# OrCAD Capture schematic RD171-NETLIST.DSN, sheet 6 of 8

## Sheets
6 3: size A3
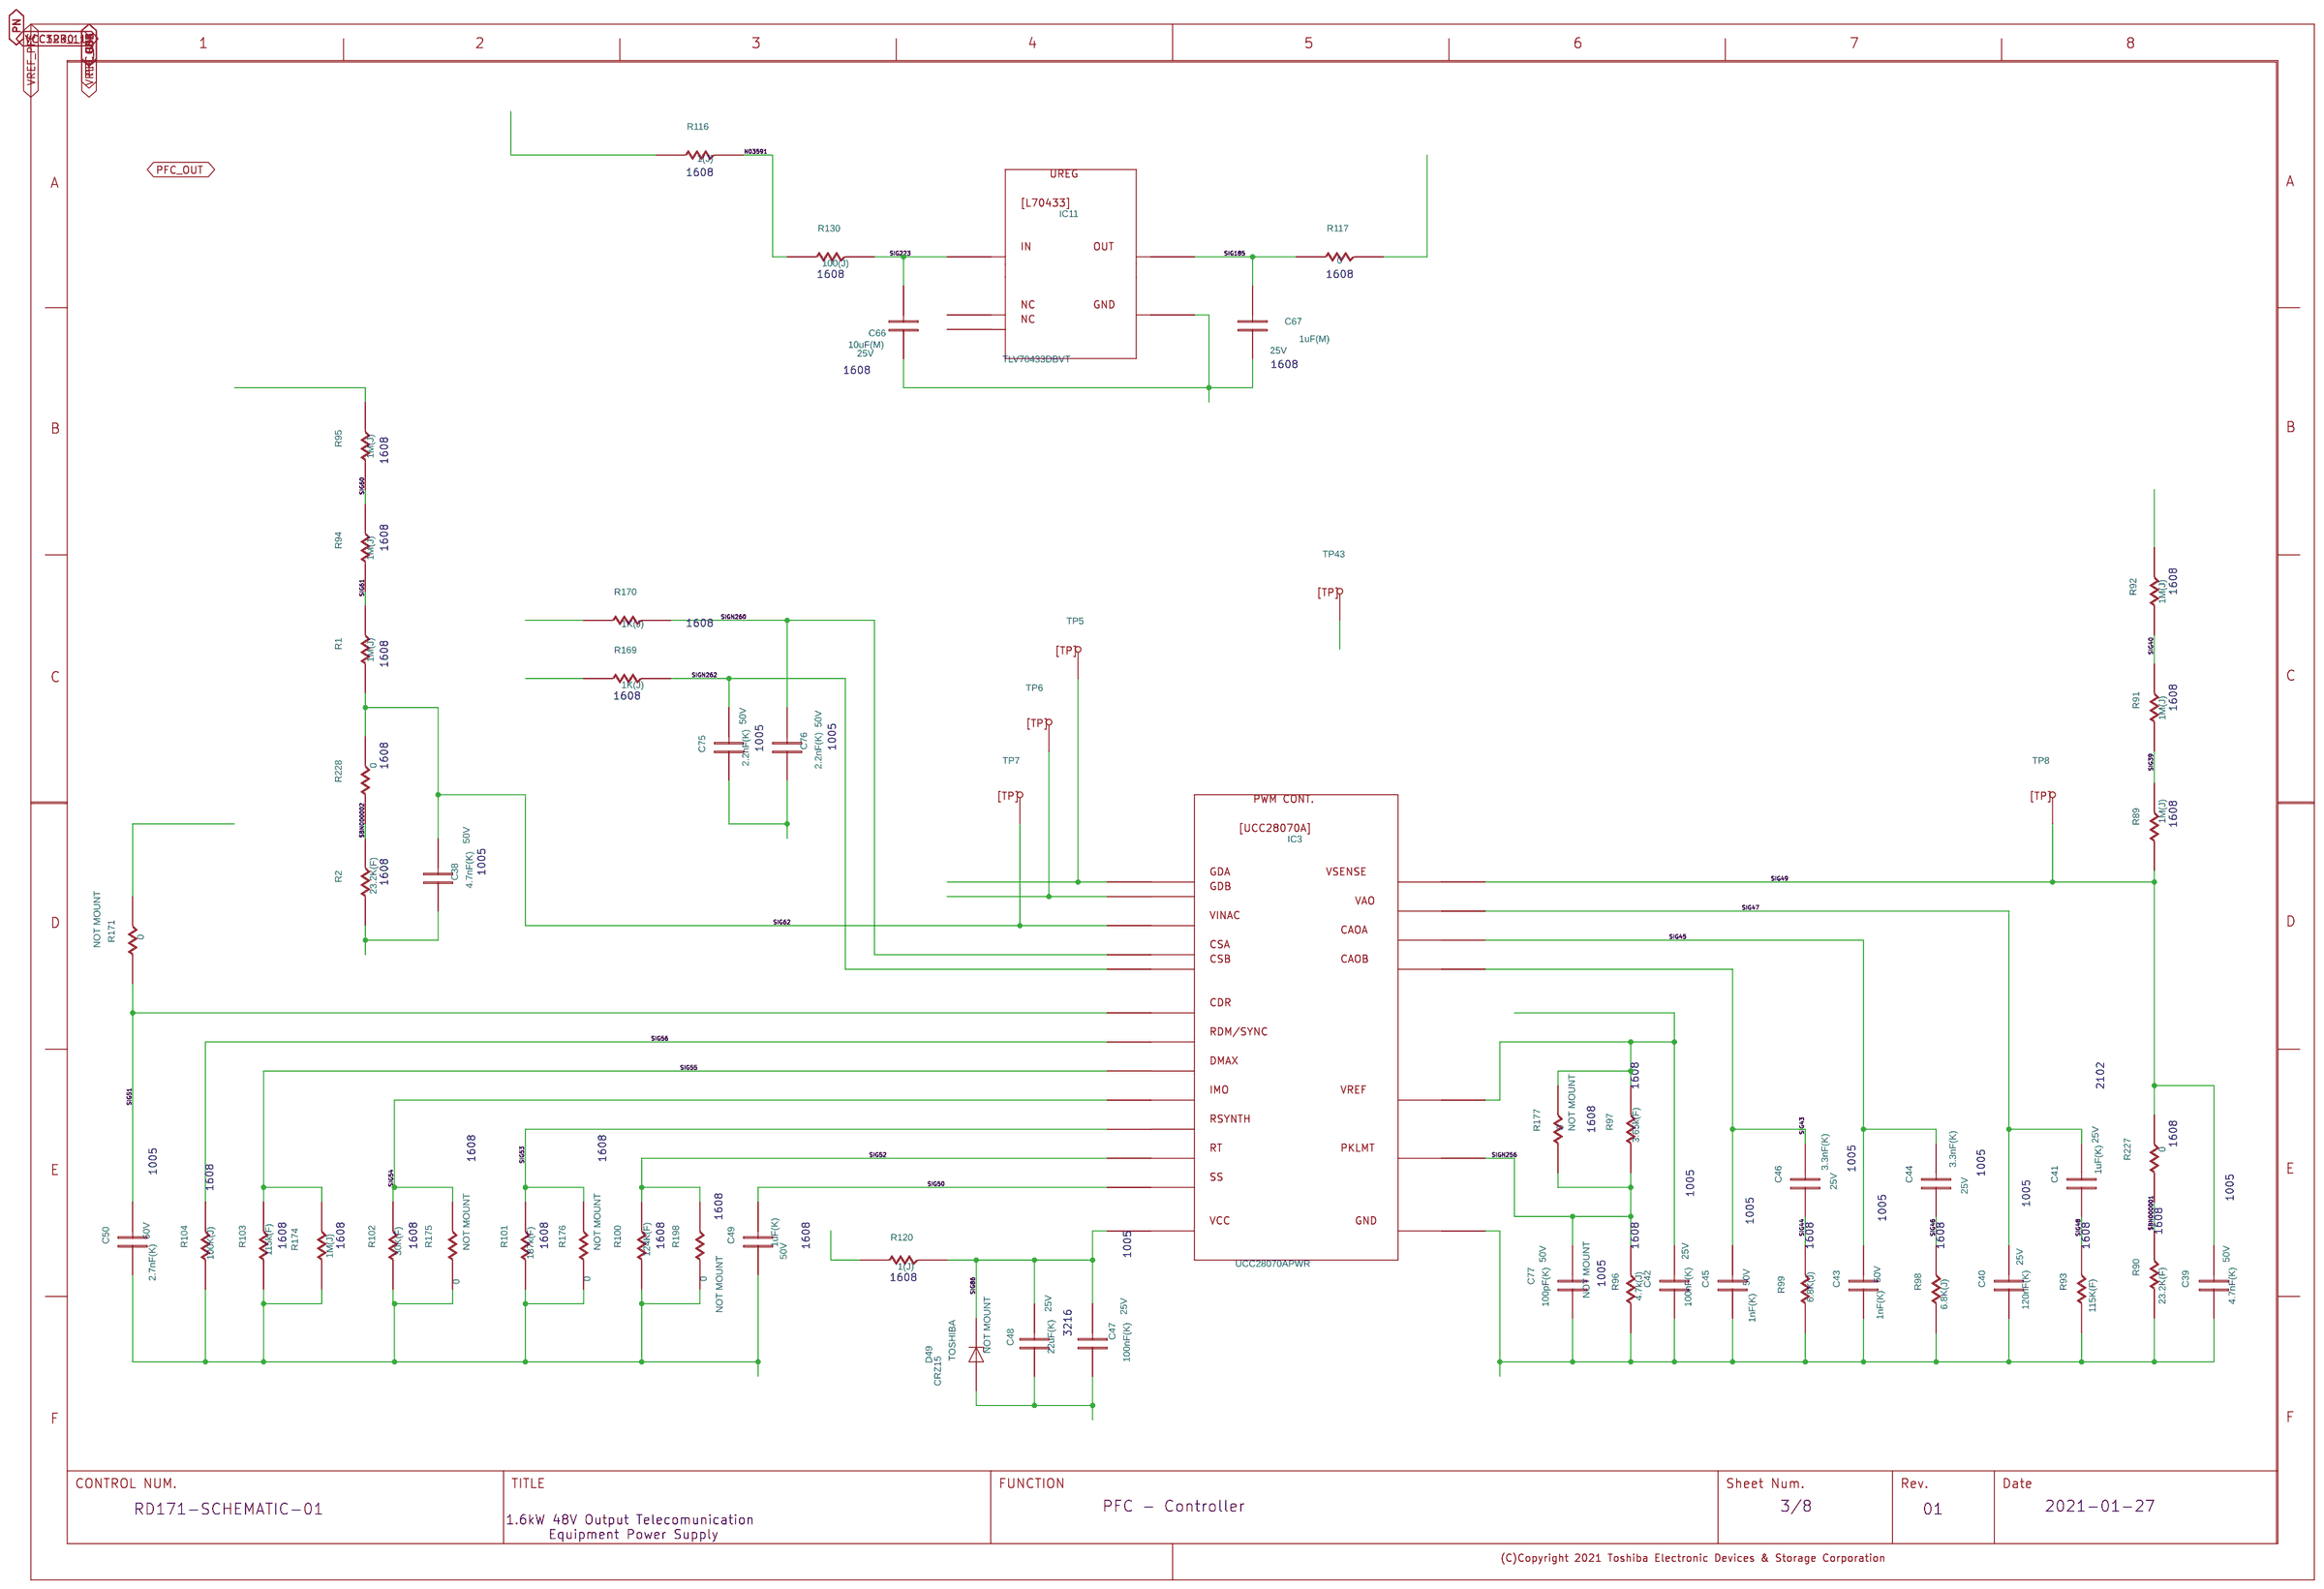
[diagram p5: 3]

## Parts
C38  4.7nF
C39  4.7nF
C40  120nF
C41  1uF
C42  100nF
C43  1nF
C44  3.3nF
C45  1nF
C46  3.3nF
C47  100nF
C48  22uF
C49  1uF  [C1608JB1H105K080AB]
C50  2.7nF
C66  10uF
C67  1uF
C75  2.2nF
C76  2.2nF
C77  100pF
D49  D49  [CRZ15]
IC3  IC3  [UCC28070APWR]
IC11  IC11  [TLV70433DBVT]
R1  1M
R2  23.2K
R89  1M
R90  23.2K
R91  1M
R92  1M
R93  115k
R94  1M
R95  1M
R96  4.3k
R97  3.65k
R98  6.8k
R99  6.8k
R100  124k
R101  187k
R102  30k
R103  115k
R104  100k
R116  1
R117  0
R120  1
R130  100
R169  1k
R170  1k
R171  0
R174  1M
R175  0
R176  0
R177  0
R198  0
R227  0
R228  0
TP5  TP5  [HK-2-S]
TP6  TP6  [HK-2-S]
TP7  TP7  [HK-2-S]
TP8  TP8  [HK-2-S]
TP43  TP43  [LC-22-S-WHITE]
U?#5  WAKU_DEF100

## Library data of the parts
C38 = C: ADSMODELNAME: s_UMK105BJ122KV_F; CAPACITANCETOLE: K; CDMASTERCADCELG: KC0005; CHIPSIZE: 1005; COMP: PRT_52; COMPONENTNAME: C_C.Normal_package; FNLEADFREETHET1GT2GMCTH1: 2_0_N; FUNCTION: C_C.Normal_package; GCOUNT: 1; INSTANCENAME: INS2671; MAKER: TDK; MAXGCOUNT: 1; NOMINALCAPACITA: 1.2n; OUMECLASSIFICATION: ƒZƒ‰ƒ~ƒbƒNƒRƒ“ƒfƒ“ƒT; OUMEMAKER: TYD ‘¾—z—U“d; OUMEMAKERKATAMEI: UMK105BJ122KV-F; PARTNAME: Chip1005_GS_2; PMPRODUCTSTYPEG: HD1; QUADMODEL: CON_1.2N; RATEDVOLTAGE: 50; SIZECODESMD: 1005; TEMPCHARACTERI2: B; VAL1: 4.7nF(K); VAL2: 50V; VAL3: GRM155R71H472JA01D
C39 = C: ADSMODELNAME: s_UMK105BJ122KV_F; CAPACITANCETOLE: K; CDMASTERCADCELG: KC0005; CHIPSIZE: 1005; COMP: PRT_52; COMPONENTNAME: C_C.Normal_package; FNLEADFREETHET1GT2GMCTH1: 2_0_N; FUNCTION: C_C.Normal_package; GCOUNT: 1; INSTANCENAME: INS2681; MAKER: TDK; MAXGCOUNT: 1; NOMINALCAPACITA: 1.2n; OUMECLASSIFICATION: ƒZƒ‰ƒ~ƒbƒNƒRƒ“ƒfƒ“ƒT; OUMEMAKER: TYD ‘¾—z—U“d; OUMEMAKERKATAMEI: UMK105BJ122KV-F; PARTNAME: Chip1005_GS_2; PMPRODUCTSTYPEG: HD1; QUADMODEL: CON_1.2N; RATEDVOLTAGE: 50; SIZECODESMD: 1005; TEMPCHARACTERI2: B; VAL1: 4.7nF(K); VAL2: 50V; VAL3: GRM155R71H472JA01D
C40 = C: ADSMODELNAME: s_GCM188R71E154KA37D; CAPACITANCETOLE: K; CDMASTERCADCELG: KC0008; CHIPSIZE: 1608; COMP: PRT_48; COMPONENTNAME: C_C.Normal_package; FNLEADFREETHET1GT2GMCTH1: N_N_N; FUNCTION: C_C.Normal_package; GCOUNT: 1; INSTANCENAME: INS2519; MAKER: MURATA; MAXGCOUNT: 1; NOMINALCAPACITA: 150n; OUMECLASSIFICATION: ƒZƒ‰ƒ~ƒbƒNƒRƒ“ƒfƒ“ƒT; OUMEMAKER: MRT ºc»ì; OUMEMAKERKATAMEI: GCM188R71E154KA37D; PARTNAME: Chip1608_GS_1; PMPRODUCTSTYPEG: DME; QUADMODEL: CON_150N; RATEDVOLTAGE: 25; SIZECODESMD: 1608; VAL1: 120nF(K); VAL2: 25V; VAL3: GRM188R71E124KA01D
C41 = C: ADSMODELNAME: s_GCM31CR71H155KA55L; CAPACITANCETOLE: K; CHIPSIZE: 2012; COMP: PRT_32; COMPONENTNAME: C_C.Normal_package; FUNCTION: C_C.Normal_package; GCOUNT: 1; INSTANCENAME: INS2529; MAKER: TDK; MAXGCOUNT: 1; NOMINALCAPACITA: 1.5u; PARTNAME: Chip2012_GS_1; PMPRODUCTSTYPEG: DME; RATEDVOLTAGE: 50; VAL1: 1uF(K); VAL2: 25V; VAL3: C2012X7R1E105K125AB
C42 = C: ADSMODELNAME: s_GRM155R71E104KE14D; CAPACITANCETOLE: K; CDMASTERCADCELG: KC0005; CHIPSIZE: 1005; COMP: PRT_52; COMPONENTNAME: C_C.Normal_package; FNLEADFREETHET1GT2GMCTH1: N_N_N; FUNCTION: C_C.Normal_package; GCOUNT: 1; INSTANCENAME: INS2499; MAKER: TDK; MAXGCOUNT: 1; NOMINALCAPACITA: 100n; OUMECLASSIFICATION: ƒZƒ‰ƒ~ƒbƒNƒRƒ“ƒfƒ“ƒT; OUMEMAKER: MRT ºc»ì; OUMEMAKERKATAMEI: GRM155R71E104KE14D; PARTNAME: Chip1005_GS_2; QUADMODEL: CON_100N; RATEDVOLTAGE: 25; SIZECODESMD: 1005; VAL1: 100nF(K); VAL2: 25V; VAL3: C1005X7R1E104K050BB
C43 = C: ADSMODELNAME: s_UMK105BJ102KV_F; CAPACITANCETOLE: K; CDMASTERCADCELG: KC0005; CHIPSIZE: 1005; COMP: PRT_52; COMPONENTNAME: C_C.Normal_package; FNLEADFREETHET1GT2GMCTH1: 2_0_N; FUNCTION: C_C.Normal_package; GCOUNT: 1; INSTANCENAME: INS2651; MAKER: TDK; MAXGCOUNT: 1; NOMINALCAPACITA: 1n; OUMECLASSIFICATION: ƒZƒ‰ƒ~ƒbƒNƒRƒ“ƒfƒ“ƒT; OUMEMAKER: TYD ‘¾—z—U“d; OUMEMAKERKATAMEI: UMK105BJ102KV-F; PARTNAME: Chip1005_GS_2; PMPRODUCTSTYPEG: HD1-PC1; QUADMODEL: CON_1N; RATEDVOLTAGE: 50; SIZECODESMD: 1005; TEMPCHARACTERI2: B; VAL1: 1nF(K); VAL2: 50V; VAL3: UMK105BJ102KV-F
C44 = C: ADSMODELNAME: s_C1005JB1E332KT; CAPACITANCETOLE: K; CDMASTERCADCELG: KC0005; CHIPSIZE: 1005; COMP: PRT_52; COMPONENTNAME: C_C.Normal_package; FNLEADFREETHET1GT2GMCTH1: N_N_N; FUNCTION: C_C.Normal_package; GCOUNT: 1; INSTANCENAME: INS2893; MAKER: TDK; MAXGCOUNT: 1; NOMINALCAPACITA: 3.3n; OUMECLASSIFICATION: ƒZƒ‰ƒ~ƒbƒNƒRƒ“ƒfƒ“ƒT; OUMEMAKER: TDK ‚s‚c‚j; OUMEMAKERKATAMEI: C1005JB1E332KT; PARTNAME: Chip1005_GS_2; QUADMODEL: CON_3.3N; RATEDVOLTAGE: 25; SIZECODESMD: 1005; VAL1: 3.3nF(K); VAL2: 25V; VAL3: CGJ2B2X7R1E332K050BA
C45 = C: ADSMODELNAME: s_UMK105BJ102KV_F; CAPACITANCETOLE: K; CDMASTERCADCELG: KC0005; CHIPSIZE: 1005; COMP: PRT_52; COMPONENTNAME: C_C.Normal_package; FNLEADFREETHET1GT2GMCTH1: 2_0_N; FUNCTION: C_C.Normal_package; GCOUNT: 1; INSTANCENAME: INS2661; MAKER: TDK; MAXGCOUNT: 1; NOMINALCAPACITA: 1n; OUMECLASSIFICATION: ƒZƒ‰ƒ~ƒbƒNƒRƒ“ƒfƒ“ƒT; OUMEMAKER: TYD ‘¾—z—U“d; OUMEMAKERKATAMEI: UMK105BJ102KV-F; PARTNAME: Chip1005_GS_2; PMPRODUCTSTYPEG: HD1-PC1; QUADMODEL: CON_1N; RATEDVOLTAGE: 50; SIZECODESMD: 1005; TEMPCHARACTERI2: B; VAL1: 1nF(K); VAL2: 50V; VAL3: UMK105BJ102KV-F
C46 = C: ADSMODELNAME: s_C1005JB1E332KT; CAPACITANCETOLE: K; CDMASTERCADCELG: KC0005; CHIPSIZE: 1005; COMP: PRT_52; COMPONENTNAME: C_C.Normal_package; FNLEADFREETHET1GT2GMCTH1: N_N_N; FUNCTION: C_C.Normal_package; GCOUNT: 1; INSTANCENAME: INS2883; MAKER: TDK; MAXGCOUNT: 1; NOMINALCAPACITA: 3.3n; OUMECLASSIFICATION: ƒZƒ‰ƒ~ƒbƒNƒRƒ“ƒfƒ“ƒT; OUMEMAKER: TDK ‚s‚c‚j; OUMEMAKERKATAMEI: C1005JB1E332KT; PARTNAME: Chip1005_GS_2; QUADMODEL: CON_3.3N; RATEDVOLTAGE: 25; SIZECODESMD: 1005; VAL1: 3.3nF(K); VAL2: 25V; VAL3: CGJ2B2X7R1E332K050BA
C47 = C: ADSCNVFLAG: ON; ADSCOMPONENTNAME: C_1005; ADSMODELNAME: s_GRM155R71E104KE14D; CAPACITANCETOLE: K; CDMASTERCADCELG: KC0005; CHIPSIZE: 1005; COMP: PRT_52; COMPONENTNAME: C_C.Normal_package; FNLEADFREETHET1GT2GMCTH1: N_N_N; FUNCTION: C_C.Normal_package; GCOUNT: 1; ICX_PART_MODEL: CON_100N; INSTANCENAME: INS2489; MAKER: TDK; MAXGCOUNT: 1; NOMINALCAPACITA: 100n; OUMECLASSIFICATION: ƒZƒ‰ƒ~ƒbƒNƒRƒ“ƒfƒ“ƒT; OUMEMAKER: MRT ºc»ì; OUMEMAKERKATAMEI: GRM155R71E104KE14D; PARTNAME: Chip1005_GS_2; QUADMODEL: CON_100N; RATEDVOLTAGE: 25; SIZECODESMD: 1005; SQ_PART_MODEL: CON_100N; VAL1: 100nF(K); VAL2: 25V; VAL3: C1005X7R1E104K050BB
C48 = C: ADSMODELNAME: s_GRM31CB31E226ME15D; CAPACITANCETOLE: M; CDMASTERCADCELG: KC0014; CHIPSIZE: 3216; COMP: PRT_51; COMPONENTNAME: C_C.Normal_package; FNLEADFREETHET1GT2GMCTH1: N_N_N; FUNCTION: C_C.Normal_package; GCOUNT: 1; INSTANCENAME: INS2863; MAKER: MURATA; MAXGCOUNT: 1; NOMINALCAPACITA: 22u; OUMECLASSIFICATION: ƒZƒ‰ƒ~ƒbƒNƒRƒ“ƒfƒ“ƒT; OUMEMAKER: MRT ºc»ì; OUMEMAKERKATAMEI: GRM31CB31E226ME15D; PARTNAME: Chip3216_GS_1; QUADMODEL: CON_22U; RATEDVOLTAGE: 25; SIZECODESMD: 3216; TEMPCHARACTERI2: B; VAL1: 22uF(K); VAL2: 25V; VAL3: GRM31CR61E226KE15L
C49 = C: ADSMODELNAME: s_GRM155R71E104KE14D; CAPACITANCETOLE: K; CDMASTERCADCELG: KC0005; CHIPSIZE: 1005; COMP: PRT_52; COMPONENTNAME: C_C.Normal_package; FNLEADFREETHET1GT2GMCTH1: N_N_N; FUNCTION: C_C.Normal_package; GCOUNT: 1; INSTANCENAME: INS2479; MAKER: TDK; MAXGCOUNT: 1; NOMINALCAPACITA: 100n; OUMECLASSIFICATION: ƒZƒ‰ƒ~ƒbƒNƒRƒ“ƒfƒ“ƒT; OUMEMAKER: MRT ºc»ì; OUMEMAKERKATAMEI: GRM155R71E104KE14D; PARTNAME: Chip1608_GS_1; QUADMODEL: CON_100N; RATEDVOLTAGE: 25; SIZECODESMD: 1005; VAL1: 1uF(K); VAL2: 50V
C50 = C: ADSMODELNAME: s_UMK105BJ272KV_F; CAPACITANCETOLE: K; CDMASTERCADCELG: DC834K; CHIPSIZE: 1005; COMP: PRT_52; COMPONENTNAME: C_C.Normal_package; FNLEADFREETHET1GT2GMCTH1: 3_0_N; FUNCTION: C_C.Normal_package; GCOUNT: 1; INSTANCENAME: INS2711; MAKER: TDK; MAXGCOUNT: 1; NOMINALCAPACITA: 2.7n; OUMECLASSIFICATION: ƒZƒ‰ƒ~ƒbƒNƒRƒ“ƒfƒ“ƒT; OUMEMAKER: TYD ‘¾—z—U“d; OUMEMAKERKATAMEI: UMK105BJ272KV-F; PARTNAME: Chip1005_GS_2; PMPRODUCTSTYPEG: PC1; QUADMODEL: CON_2.7N; RATEDVOLTAGE: 50; SIZECODESMD: 1005; TEMPCHARACTERI2: B; VAL1: 2.7nF(K); VAL2: 50V; VAL3: UMK105BJ272KV-F
C66 = C: ADSMODELNAME: s_ZRB18AR61E106ME01L; CAPACITANCETOLE: M; CDMASTERCADCELG: KC0167; CHIPSIZE: 1608; COMP: PRT_48; COMPONENTNAME: C_C.Normal_package; FNLEADFREETHET1GT2GMCTH1: N_N_N; FUNCTION: C_C.Normal_package; GCOUNT: 1; INSTANCENAME: INS2953; MAKER: TDK; MAXGCOUNT: 1; NOMINALCAPACITA: 10u; OUMECLASSIFICATION: ƒZƒ‰ƒ~ƒbƒNƒRƒ“ƒfƒ“ƒT; OUMEMAKER: MRT ºc»ì; OUMEMAKERKATAMEI: ZRB18AR61E106ME01L; PARTNAME: Chip1608_GS_1; QUADMODEL: CON_10U; RATEDVOLTAGE: 25; SIZECODESMD: 1608; VAL1: 10uF(M); VAL2: 25V; VAL3: C1608X5R1E106M080AC
C67 = C: ADSCNVFLAG: ON; ADSCOMPONENTNAME: C_1608; ADSMODELNAME: s_GRM185B31E105KA12D; CAPACITANCETOLE: K; CDMASTERCADCELG: KC0008; CHIPSIZE: 1005; COMP: PRT_52; COMPONENTNAME: C_C.Normal_package; FNLEADFREETHET1GT2GMCTH1: N_N_N; FUNCTION: C_C.Normal_package; GCOUNT: 1; ICX_PART_MODEL: CON_1U; INSTANCENAME: INS2963; MAKER: TDK; MAXGCOUNT: 1; NOMINALCAPACITA: 1u; OUMECLASSIFICATION: ƒZƒ‰ƒ~ƒbƒNƒRƒ“ƒfƒ“ƒT; OUMEMAKER: MRT ºc»ì; OUMEMAKERKATAMEI: GRM185B31E105KA12D; PARTNAME: Chip1005_GS_2; PMPRODUCTSTYPEG: HD1; QUADMODEL: CON_1U; RATEDVOLTAGE: 25; SIZECODESMD: 1608; SQ_PART_MODEL: CON_1U; TEMPCHARACTERI2: B; VAL1: 1uF(M); VAL2: 25V; VAL3: C1005X5R1E105M050BC
C75 = C: ADSMODELNAME: s_UMK105BJ222KV_F; CAPACITANCETOLE: K; CDMASTERCADCELG: KC0005; CHIPSIZE: 1005; COMP: PRT_52; COMPONENTNAME: C_C.Normal_package; FNLEADFREETHET1GT2GMCTH1: 2_0_N; FUNCTION: C_C.Normal_package; GCOUNT: 1; INSTANCENAME: INS2691; MAKER: TDK; MAXGCOUNT: 1; NOMINALCAPACITA: 2.2n; OUMECLASSIFICATION: ƒZƒ‰ƒ~ƒbƒNƒRƒ“ƒfƒ“ƒT; OUMEMAKER: TYD ‘¾—z—U“d; OUMEMAKERKATAMEI: UMK105BJ222KV-F; PARTNAME: Chip1005_GS_2; PMPRODUCTSTYPEG: HD1-PC1; QUADMODEL: CON_2.2N; RATEDVOLTAGE: 50; SIZECODESMD: 1005; TEMPCHARACTERI2: B; VAL1: 2.2nF(K); VAL2: 50V; VAL3: UMK105BJ222KV-F
C76 = C: ADSMODELNAME: s_UMK105BJ222KV_F; CAPACITANCETOLE: K; CDMASTERCADCELG: KC0005; CHIPSIZE: 1005; COMP: PRT_52; COMPONENTNAME: C_C.Normal_package; FNLEADFREETHET1GT2GMCTH1: 2_0_N; FUNCTION: C_C.Normal_package; GCOUNT: 1; INSTANCENAME: INS2701; MAKER: TDK; MAXGCOUNT: 1; NOMINALCAPACITA: 2.2n; OLDCOMPONENTID: 99; OUMECLASSIFICATION: ƒZƒ‰ƒ~ƒbƒNƒRƒ“ƒfƒ“ƒT; OUMEMAKER: TYD ‘¾—z—U“d; OUMEMAKERKATAMEI: UMK105BJ222KV-F; PARTNAME: Chip1005_GS_2; PMPRODUCTSTYPEG: HD1-PC1; QUADMODEL: CON_2.2N; RATEDVOLTAGE: 50; SIZECODESMD: 1005; TEMPCHARACTERI2: B; VAL1: 2.2nF(K); VAL2: 50V; VAL3: UMK105BJ222KV-F
C77 = C: CHIPSIZE: 1608; COMP: PRT_48; COMPONENTNAME: C_C.Normal_package; FUNCTION: C_C.Normal_package; INSTANCENAME: INS2539; MAKER: MURATA; NOTMOUNT: NOT MOUNT; PARTNAME: Chip1608_GS_1; VAL1: 100pF(K); VAL2: 50V; VAL3: GRM1885C1H101JA01D
D49 = ZD: ADSMODELNAME: s_CRZ15; CDMASTERCADCELG: MMK0167; COMP: PRT_6; COMPONENTNAME: ZD_ZD.Normal_package; FNLEADFREETHET1GT2GMCTH1: N_N_N; FORWARDVOLTAGEM: 0; FUNCTION: ZD_ZD.Normal_package; GCOUNT: 1; INSTANCENAME: INS2465; MAXAVERAGEFORWA: 0; MAXGCOUNT: 1; MAXREPETITIVEPE: 0; MAXREVERSEVOLTA: 0; MOUNTINGFORMSMD: SMD; NOTMOUNT: NOT MOUNT; OUMECLASSIFICATION: èd³_CI[h; OUMEMAKER: TSB “ŒŽÅ; OUMEPARTTYPE: D; PARTNAME: CRZ15_TS_A; PEAKFORWARDVOLT: 0; REVERSECURRENT: 0; USERCOMPTEXT3: TOSHIBA; ZENERVOLTAGEMAX: 16.5
IC3 = L28070: COMP: PRT_59; COMPONENTNAME: L28070_L28070.Normal_package; FUNCTION: L28070_L28070.Normal_package; INSTANCENAME: INS2419; MAKER: TEXAS; PARTNAME: UCC28070APW_TI; SAVECOUNT: 1; UPDATEDATE: 2020/07/08; UPDATETIME: 16:40:04
IC11 = L70433: COMP: PRT_10; COMPONENTNAME: L70433_L70433.Normal_package; FUNCTION: L70433_L70433.Normal_package; INSTANCENAME: INS3049; MAKER: TEXAS; PARTNAME: TLV70433DBVT_TI; SAVECOUNT: 1; UPDATEDATE: 2020/07/08; UPDATETIME: 16:40:04
R1 = R: ADSMODELNAME: s_RK73H1JTTD1004F; CDMASTERCADCELG: KC0167; CHIPSIZE: 1608; COMP: PRT_8; COMPONENTNAME: R_R.Normal_package; FNLEADFREETHET1GT2GMCTH1: N_N_N; FUNCTION: R_R.Normal_package; GCOUNT: 1; INSTANCENAME: INS2763; MAKER: KOA; MAXGCOUNT: 1; MOUNTINGFORMSMD: SMD; OUMECLASSIFICATION: \ÊÀpÅèïRí; OUMEMAKER: KOA R[A; OUMEMAKERKATAMEI: RK73H1JTTD1004F; PARTNAME: Chip1608_GS_1; POWERRATING: 100m; QUADMODEL: RES_1M; RESISTANCETOLER: F; SIZECODESMD: 1608; VAL1: 1M(J); VAL2: 100mW,}5%; VAL3: RK73B1JTTD105J
R2 = R: ADSMODELNAME: s_ERJ3GEYJ243V; CDMASTERCADCELG: KC0008; CHIPSIZE: 1608; COMP: PRT_8; COMPONENTNAME: R_R.Normal_package; FNLEADFREETHET1GT2GMCTH1: 3_1_N; FUNCTION: R_R.Normal_package; GCOUNT: 1; INSTANCENAME: INS2773; MAKER: PANASONIC; MAXGCOUNT: 1; MOUNTINGFORMSMD: SMD; NOMINALRESISTAN: 24K; OUMECLASSIFICATION: \ÊÀpÅèïRí; OUMEMAKER: NAE pi\jbNGNgjbNfoCX; OUMEMAKERKATAMEI: ERJ3GEYJ243V; PARTNAME: Chip1608_GS_1; POWERRATING: 63m; QUADMODEL: RES_24K; RESISTANCETOLER: J; SIZECODESMD: 1608; VAL1: 23.2K(F); VAL2: 100mW,}1%; VAL3: ERJ-3EKF2322V
R89 = R: ADSMODELNAME: s_RK73H1JTTD1004F; CDMASTERCADCELG: KC0167; CHIPSIZE: 1608; COMP: PRT_8; COMPONENTNAME: R_R.Normal_package; FNLEADFREETHET1GT2GMCTH1: N_N_N; FUNCTION: R_R.Normal_package; GCOUNT: 1; INSTANCENAME: INS2813; MAKER: KOA; MAXGCOUNT: 1; MOUNTINGFORMSMD: SMD; OUMECLASSIFICATION: \ÊÀpÅèïRí; OUMEMAKER: KOA R[A; OUMEMAKERKATAMEI: RK73H1JTTD1004F; PARTNAME: Chip1608_GS_1; POWERRATING: 100m; QUADMODEL: RES_1M; RESISTANCETOLER: F; SIZECODESMD: 1608; VAL1: 1M(J); VAL2: 100mW; VAL3: RK73B1JTTD105J
R90 = R: ADSMODELNAME: s_ERJ3EKF2202V; CDMASTERCADCELG: KC0008; CHIPSIZE: 1608; COMP: PRT_8; COMPONENTNAME: R_R.Normal_package; FNLEADFREETHET1GT2GMCTH1: N_N_N; FUNCTION: R_R.Normal_package; GCOUNT: 1; INSTANCENAME: INS2923; MAKER: PANASONIC; MAXGCOUNT: 1; MOUNTINGFORMSMD: SMD; NOMINALRESISTAN: 22K; OUMECLASSIFICATION: \ÊÀpÅèïRí; OUMEMAKER: NAE pi\jbNGNgjbNfoCX; OUMEMAKERKATAMEI: ERJ3EKF2202V; PARTNAME: Chip1608_GS_1; POWERRATING: 100m; QUADMODEL: RES_22K; RESISTANCETOLER: F; SIZECODESMD: 1608; VAL1: 23.2K(F); VAL2: 100mW,}1%; VAL3: ERJ-3EKF2322V
R91 = R: ADSMODELNAME: s_RK73H1JTTD1004F; CDMASTERCADCELG: KC0167; CHIPSIZE: 1608; COMP: PRT_8; COMPONENTNAME: R_R.Normal_package; FNLEADFREETHET1GT2GMCTH1: N_N_N; FUNCTION: R_R.Normal_package; GCOUNT: 1; INSTANCENAME: INS2803; MAKER: KOA; MAXGCOUNT: 1; MOUNTINGFORMSMD: SMD; OUMECLASSIFICATION: \ÊÀpÅèïRí; OUMEMAKER: KOA R[A; OUMEMAKERKATAMEI: RK73H1JTTD1004F; PARTNAME: Chip1608_GS_1; POWERRATING: 100m; QUADMODEL: RES_1M; RESISTANCETOLER: F; SIZECODESMD: 1608; VAL1: 1M(J); VAL2: 100mW,}5%; VAL3: RK73B1JTTD105J
R92 = R: ADSMODELNAME: s_RK73H1JTTD1004F; CDMASTERCADCELG: KC0167; CHIPSIZE: 1608; COMP: PRT_8; COMPONENTNAME: R_R.Normal_package; FNLEADFREETHET1GT2GMCTH1: N_N_N; FUNCTION: R_R.Normal_package; GCOUNT: 1; INSTANCENAME: INS2823; MAKER: KOA; MAXGCOUNT: 1; MOUNTINGFORMSMD: SMD; OUMECLASSIFICATION: \ÊÀpÅèïRí; OUMEMAKER: KOA R[A; OUMEMAKERKATAMEI: RK73H1JTTD1004F; PARTNAME: Chip1608_GS_1; POWERRATING: 100m; QUADMODEL: RES_1M; RESISTANCETOLER: F; SIZECODESMD: 1608; VAL1: 1M(J); VAL2: 100mW,}5%; VAL3: RK73B1JTTD105J
R93 = R: ADSMODELNAME: s_ERJ3EKF1103V; CDMASTERCADCELG: KC0008; CHIPSIZE: 1608; COMP: PRT_8; COMPONENTNAME: R_R.Normal_package; FNLEADFREETHET1GT2GMCTH1: N_N_N; FUNCTION: R_R.Normal_package; GCOUNT: 1; INSTANCENAME: INS2913; MAKER: PANASONIC; MAXGCOUNT: 1; MOUNTINGFORMSMD: SMD; NOMINALRESISTAN: 110K; OUMECLASSIFICATION: \ÊÀpÅèïRí; OUMEMAKER: NAE pi\jbNGNgjbNfoCX; OUMEMAKERKATAMEI: ERJ3EKF1103V; PARTNAME: Chip1608_GS_1; POWERRATING: 100m; QUADMODEL: RES_110K; RESISTANCETOLER: F; SIZECODESMD: 1608; VAL1: 115K(F); VAL2: 100mW,}1%; VAL3: ERJ-3EKF1153V
R94 = R: ADSMODELNAME: s_RK73H1JTTD1004F; CDMASTERCADCELG: KC0167; CHIPSIZE: 1608; COMP: PRT_8; COMPONENTNAME: R_R.Normal_package; FNLEADFREETHET1GT2GMCTH1: N_N_N; FUNCTION: R_R.Normal_package; GCOUNT: 1; INSTANCENAME: INS2743; MAKER: KOA; MAXGCOUNT: 1; MOUNTINGFORMSMD: SMD; OUMECLASSIFICATION: \ÊÀpÅèïRí; OUMEMAKER: KOA R[A; OUMEMAKERKATAMEI: RK73H1JTTD1004F; PARTNAME: Chip1608_GS_1; POWERRATING: 100m; QUADMODEL: RES_1M; RESISTANCETOLER: F; SIZECODESMD: 1608; VAL1: 1M(J); VAL2: 100mW,}5%; VAL3: RK73B1JTTD105J
R95 = R: ADSMODELNAME: s_RK73H1JTTD1004F; CDMASTERCADCELG: KC0167; CHIPSIZE: 1608; COMP: PRT_8; COMPONENTNAME: R_R.Normal_package; FNLEADFREETHET1GT2GMCTH1: N_N_N; FUNCTION: R_R.Normal_package; GCOUNT: 1; INSTANCENAME: INS2753; MAKER: KOA; MAXGCOUNT: 1; MOUNTINGFORMSMD: SMD; OUMECLASSIFICATION: \ÊÀpÅèïRí; OUMEMAKER: KOA R[A; OUMEMAKERKATAMEI: RK73H1JTTD1004F; PARTNAME: Chip1608_GS_1; POWERRATING: 100m; QUADMODEL: RES_1M; RESISTANCETOLER: F; SIZECODESMD: 1608; VAL1: 1M(J); VAL2: 100mW,}5%; VAL3: RK73B1JTTD105J
R96 = R: CHIPSIZE: 1608; COMP: PRT_8; COMPONENTNAME: R_R.Normal_package; FUNCTION: R_R.Normal_package; INSTANCENAME: INS2571; MAKER: KOA; PARTNAME: Chip1608_GS_1; VAL1: 4.7k(J); VAL2: 100mW,}5%; VAL3: RK73B1JTTD392J
R97 = R: CHIPSIZE: 1608; COMP: PRT_8; COMPONENTNAME: R_R.Normal_package; FUNCTION: R_R.Normal_package; INSTANCENAME: INS2561; MAKER: PANASONIC; PARTNAME: Chip1608_GS_1; VAL1: 3.65k(F); VAL2: 100mW,}1%; VAL3: ERJ-3EKF3651V
R98 = R: ADSMODELNAME: s_RN73H1JTTD6801B10; CDMASTERCADCELG: KCK0203; CHIPSIZE: 1608; COMP: PRT_8; COMPONENTNAME: R_R.Normal_package; FNLEADFREETHET1GT2GMCTH1: N_N_N; FUNCTION: R_R.Normal_package; GCOUNT: 1; INSTANCENAME: INS2903; MAKER: KOA; MAXGCOUNT: 1; MOUNTINGFORMSMD: SMD; NOMINALRESISTAN: 6.8K; OUMECLASSIFICATION: \ÊÀpÅèïRí; OUMEMAKER: KOA R[A; OUMEMAKERKATAMEI: RN73H1JTTD6801B10; PARTNAME: Chip1608_GS_1; PMPRODUCTSTYPEG: DME; POWERRATING: 100m; QUADMODEL: RES_6.8K; RESISTANCETOLER: B; SIZECODESMD: 1608; VAL1: 6.8K(J); VAL2: 100mW,}5%; VAL3: RK73B1JTTD682J
R99 = R: ADSMODELNAME: s_RN73H1JTTD6801B10; CDMASTERCADCELG: KCK0203; CHIPSIZE: 1608; COMP: PRT_8; COMPONENTNAME: R_R.Normal_package; FNLEADFREETHET1GT2GMCTH1: N_N_N; FUNCTION: R_R.Normal_package; GCOUNT: 1; INSTANCENAME: INS2873; MAKER: KOA; MAXGCOUNT: 1; MOUNTINGFORMSMD: SMD; NOMINALRESISTAN: 6.8K; OUMECLASSIFICATION: \ÊÀpÅèïRí; OUMEMAKER: KOA R[A; OUMEMAKERKATAMEI: RN73H1JTTD6801B10; PARTNAME: Chip1608_GS_1; PMPRODUCTSTYPEG: DME; POWERRATING: 100m; QUADMODEL: RES_6.8K; RESISTANCETOLER: B; SIZECODESMD: 1608; VAL1: 6.8K(J); VAL2: 100mW,}5%; VAL3: RK73B1JTTD682J
R100 = R: ADSMODELNAME: s_ERJ3EKF1203V; CDMASTERCADCELG: KC0008; CHIPSIZE: 1608; COMP: PRT_8; COMPONENTNAME: R_R.Normal_package; FNLEADFREETHET1GT2GMCTH1: N_N_N; FUNCTION: R_R.Normal_package; GCOUNT: 1; INSTANCENAME: INS2853; MAKER: PANASONIC; MAXGCOUNT: 1; MOUNTINGFORMSMD: SMD; NOMINALRESISTAN: 120K; OUMECLASSIFICATION: \ÊÀpÅèïRí; OUMEMAKER: NAE pi\jbNGNgjbNfoCX; OUMEMAKERKATAMEI: ERJ3EKF1203V; PARTNAME: Chip1608_GS_1; POWERRATING: 100m; QUADMODEL: RES_120K; RESISTANCETOLER: F; SIZECODESMD: 1608; VAL1: 124K(F); VAL2: 100mW,}1; VAL3: ERJ-3EKF1243V
R101 = R: CHIPSIZE: 1608; COMP: PRT_8; COMPONENTNAME: R_R.Normal_package; FUNCTION: R_R.Normal_package; INSTANCENAME: INS2581; MAKER: PANASONIC; PARTNAME: Chip1608_GS_1; VAL1: 187k(F); VAL2: 100mW,}1%; VAL3: ERJ-3EKF1873V
R102 = R: ADSMODELNAME: s_RN73H1JTTD3002B10; CDMASTERCADCELG: KC0008; CHIPSIZE: 1608; COMP: PRT_8; COMPONENTNAME: R_R.Normal_package; FNLEADFREETHET1GT2GMCTH1: N_N_N; FUNCTION: R_R.Normal_package; GCOUNT: 1; INSTANCENAME: INS2843; MAKER: KOA; MAXGCOUNT: 1; MOUNTINGFORMSMD: SMD; NOMINALRESISTAN: 30K; OUMECLASSIFICATION: \ÊÀpÅèïRí; OUMEMAKER: KOA R[A; OUMEMAKERKATAMEI: RN73H1JTTD3002B10; PARTNAME: Chip1608_GS_1; POWERRATING: 100m; QUADMODEL: RES_30K; RESISTANCETOLER: B; SIZECODESMD: 1608; VAL1: 30K(F); VAL2: 100mW,}1%; VAL3: RK73H1JTTD3002F
R103 = R: CHIPSIZE: 1608; COMP: PRT_8; COMPONENTNAME: R_R.Normal_package; FUNCTION: R_R.Normal_package; INSTANCENAME: INS2551; MAKER: PANASONIC; PARTNAME: Chip1608_GS_1; VAL1: 115k(F); VAL2: 100mW,}1%; VAL3: ERJ-3EKF1153V
R104 = R: ADSMODELNAME: s_RK73B1JTTD104G; CDMASTERCADCELG: KC0008; CHIPSIZE: 1608; COMP: PRT_8; COMPONENTNAME: R_R.Normal_package; FNLEADFREETHET1GT2GMCTH1: N_N_N; FUNCTION: R_R.Normal_package; GCOUNT: 1; INSTANCENAME: INS2833; MAKER: KOA; MAXGCOUNT: 1; MOUNTINGFORMSMD: SMD; NOMINALRESISTAN: 100K; OUMECLASSIFICATION: \ÊÀpÅèïRí; OUMEMAKER: KOA R[A; OUMEMAKERKATAMEI: RK73B1JTTD104G; PARTNAME: Chip1608_GS_1; POWERRATING: 100m; QUADMODEL: RES_100K; RESISTANCETOLER: G; SIZECODESMD: 1608; VAL1: 100K(J); VAL2: 100mW,}5%; VAL3: RK73B1JTTD104J
R116 = R: ADSMODELNAME: s_ERJ3GEYJ1R0V; CDMASTERCADCELG: KC0008; CHIPSIZE: 1608; COMP: PRT_8; COMPONENTNAME: R_R.Normal_package; FNLEADFREETHET1GT2GMCTH1: 2_1_N; FUNCTION: R_R.Normal_package; INSTANCENAME: INS2943; MAKER: PANASONIC; MOUNTINGFORMSMD: SMD; OUMECLASSIFICATION: \ÊÀpÅèïRí; OUMEMAKER: NAE pi\jbNGNgjbNfoCX; OUMEMAKERKATAMEI: ERJ3GEYJ1R0V; PARTNAME: Chip1608_GS_1; PMPRODUCTSTYPEG: PC1; POWERRATING: 63m; QUADMODEL: RES_1; RESISTANCETOLER: J; SIZECODESMD: 1608; VAL1: 1(J); VAL2: 100mW,}5%; VAL3: ERJ-3GEYJ1R0V
R117 = R: ADSCNVFLAG: ON; ADSCOMPONENTNAME: R_1005; ADSMODELNAME: s_ERJ2GE0R00X; CDMASTERCADCELG: KC0005; CHIPSIZE: 1608; COMP: PRT_8; COMPONENTNAME: R_R.Normal_package; FNLEADFREETHET1GT2GMCTH1: 2_1_N; FUNCTION: R_R.Normal_package; GCOUNT: 1; ICX_PART_MODEL: RES_0; INSTANCENAME: INS2983; MAKER: KOA; MAXGCOUNT: 1; MOUNTINGFORMSMD: SMD; OUMECLASSIFICATION: \ÊÀpÅèïRí; OUMEMAKER: NAE pi\jbNGNgjbNfoCX; OUMEMAKERKATAMEI: ERJ2GE0R00X; PARTNAME: Chip1608_GS_1; PMPRODUCTSTYPEG: HD1-PC1; POWERRATING: 63m; QUADMODEL: RES_0; RESISTANCETOLER: X; SIZECODESMD: 1005; SQ_PART_MODEL: RES_0; VAL2: 100mW; VAL3: RK73Z1JTTD
R120 = R: ADSMODELNAME: s_ERJ3GEYJ1R0V; CDMASTERCADCELG: KC0008; CHIPSIZE: 1608; COMP: PRT_8; COMPONENTNAME: R_R.Normal_package; FNLEADFREETHET1GT2GMCTH1: 2_1_N; FUNCTION: R_R.Normal_package; INSTANCENAME: INS2509; MAKER: PANASONIC; MOUNTINGFORMSMD: SMD; OUMECLASSIFICATION: \ÊÀpÅèïRí; OUMEMAKER: NAE pi\jbNGNgjbNfoCX; OUMEMAKERKATAMEI: ERJ3GEYJ1R0V; PARTNAME: Chip1608_GS_1; PMPRODUCTSTYPEG: PC1; POWERRATING: 63m; QUADMODEL: RES_1; RESISTANCETOLER: J; SIZECODESMD: 1608; VAL1: 1(J); VAL2: 100mW,}5%; VAL3: ERJ-3GEYJ1R0V
R130 = R: ADSMODELNAME: s_ERJPA3F1000V@@; CDMASTERCADCELG: KC0165; CHIPSIZE: 1608; COMP: PRT_8; COMPONENTNAME: R_R.Normal_package; FNLEADFREETHET1GT2GMCTH1: N_N_N; FUNCTION: R_R.Normal_package; GCOUNT: 1; INSTANCENAME: INS2973; MAKER: KOA; MAXGCOUNT: 1; MOUNTINGFORMSMD: SMD; OUMECLASSIFICATION: \ÊÀpÅèïRí; OUMEMAKER: NAE pi\jbNGNgjbNfoCX; OUMEMAKERKATAMEI: ERJPA3F1000V@@; PARTNAME: Chip1608_GS_1; PMPRODUCTSTYPEG: DA; POWERRATING: 250m; QUADMODEL: RES_100; RESISTANCETOLER: F; SIZECODESMD: 1608; VAL1: 100(J); VAL2: 125mW,}5%; VAL3: RK73B1JTTD101J
R169 = R: ADSMODELNAME: s_RK73B1JTTD102G; CDMASTERCADCELG: KCK0203; CHIPSIZE: 1608; COMP: PRT_8; COMPONENTNAME: R_R.Normal_package; FNLEADFREETHET1GT2GMCTH1: N_N_N; FUNCTION: R_R.Normal_package; GCOUNT: 1; INSTANCENAME: INS2783; MAKER: KOA; MAXGCOUNT: 1; MOUNTINGFORMSMD: SMD; NOMINALRESISTAN: 1K; OUMECLASSIFICATION: \ÊÀpÅèïRí; OUMEMAKER: KOA R[A; OUMEMAKERKATAMEI: RK73B1JTTD102G; PARTNAME: Chip1608_GS_1; PMPRODUCTSTYPEG: DME; POWERRATING: 100m; QUADMODEL: RES_1K; RESISTANCETOLER: G; SIZECODESMD: 1608; VAL1: 1K(J); VAL2: 125mW,}5%; VAL3: RK73B1JTTD102J
R170 = R: ADSMODELNAME: s_RK73B1JTTD102G; CDMASTERCADCELG: KCK0203; CHIPSIZE: 1608; COMP: PRT_8; COMPONENTNAME: R_R.Normal_package; FNLEADFREETHET1GT2GMCTH1: N_N_N; FUNCTION: R_R.Normal_package; GCOUNT: 1; INSTANCENAME: INS2793; MAKER: KOA; MAXGCOUNT: 1; MOUNTINGFORMSMD: SMD; NOMINALRESISTAN: 1K; OLDCOMPONENTID: 100; OUMECLASSIFICATION: \ÊÀpÅèïRí; OUMEMAKER: KOA R[A; OUMEMAKERKATAMEI: RK73B1JTTD102G; PARTNAME: Chip1608_GS_1; PMPRODUCTSTYPEG: DME; POWERRATING: 100m; QUADMODEL: RES_1K; RESISTANCETOLER: G; SIZECODESMD: 1608; VAL1: 1K(J); VAL2: 125mW,}5%; VAL3: RK73B1JTTD102J
R171 = R: ADSMODELNAME: s_RK73Z1JTTD; CDMASTERCADCELG: KCK0203; CHIPSIZE: 1608; COMP: PRT_8; COMPONENTNAME: R_R.Normal_package; FNLEADFREETHET1GT2GMCTH1: 3_2_N; FUNCTION: R_R.Normal_package; GCOUNT: 1; INSTANCENAME: INS2731; MAKER: KOA; MAXGCOUNT: 1; MOUNTINGFORMSMD: SMD; NOTMOUNT: NOT MOUNT; OUMECLASSIFICATION: \ÊÀpÅèïRí; OUMEMAKER: KOA R[A; OUMEMAKERKATAMEI: RK73Z1JTTD; PARTNAME: Chip1608_GS_1; PMPRODUCTSTYPEG: DME-HD1-PC1; POWERRATING: 100m; QUADMODEL: RES_0; RESISTANCETOLER: X; SIZECODESMD: 1608; VAL2: 100mW; VAL3: RK73Z1JTTD
R174 = R: ADSMODELNAME: s_RK73H1JTTD1004F; CDMASTERCADCELG: KC0167; CHIPSIZE: 1608; COMP: PRT_8; COMPONENTNAME: R_R.Normal_package; FNLEADFREETHET1GT2GMCTH1: N_N_N; FUNCTION: R_R.Normal_package; GCOUNT: 1; INSTANCENAME: INS16994302; MAKER: KOA; MAXGCOUNT: 1; MOUNTINGFORMSMD: SMD; OUMECLASSIFICATION: \ÊÀpÅèïRí; OUMEMAKER: KOA R[A; OUMEMAKERKATAMEI: RK73H1JTTD1004F; PARTNAME: Chip1608_GS_1; POWERRATING: 100m; QUADMODEL: RES_1M; RESISTANCETOLER: F; SIZECODESMD: 1608; VAL1: 1M(J); VAL2: 100mW; VAL3: RK73B1JTTD105J
R175 = R: CHIPSIZE: 1608; COMP: PRT_8; COMPONENTNAME: R_R.Normal_package; FUNCTION: R_R.Normal_package; INSTANCENAME: INS2603; MAKER: KOA; NOTMOUNT: NOT MOUNT; PARTNAME: Chip1608_GS_1; VAL2: 100mW; VAL3: RK73Z1JTTD
R176 = R: CHIPSIZE: 1608; COMP: PRT_8; COMPONENTNAME: R_R.Normal_package; FUNCTION: R_R.Normal_package; INSTANCENAME: INS2615; MAKER: KOA; NOTMOUNT: NOT MOUNT; PARTNAME: Chip1608_GS_1; VAL2: 100mW; VAL3: RK73Z1JTTD
R177 = R: CHIPSIZE: 1608; COMP: PRT_8; COMPONENTNAME: R_R.Normal_package; FUNCTION: R_R.Normal_package; INSTANCENAME: INS2627; MAKER: KOA; NOTMOUNT: NOT MOUNT; PARTNAME: Chip1608_GS_1; VAL2: 100mW; VAL3: RK73Z1JTTD
R198 = R: CHIPSIZE: 1608; COMP: PRT_8; COMPONENTNAME: R_R.Normal_package; FUNCTION: R_R.Normal_package; INSTANCENAME: INS2639; MAKER: KOA; NOTMOUNT: NOT MOUNT; PARTNAME: Chip1608_GS_1; VAL2: 100mW; VAL3: RK73Z1JTTD
R227 = R: CHIPSIZE: 1608; COMP: PRT_8; COMPONENTNAME: R_R.Normal_package; FUNCTION: R_R.Normal_package; INSTANCENAME: INS2721; MAKER: KOA; PARTNAME: Chip1608_GS_1; VAL2: 100mW,}1%; VAL3: RK73H1JTTD6800F
R228 = R: CHIPSIZE: 1608; COMP: PRT_8; COMPONENTNAME: R_R.Normal_package; FUNCTION: R_R.Normal_package; INSTANCENAME: INS2933; MAKER: KOA; PARTNAME: Chip1608_GS_1; VAL2: 100mW,}1%; VAL3: RK73H1JTTD6800F
TP5 = TP: COMP: PRT_44; COMPONENTNAME: TP_TP.Normal_package; FUNCTION: TP_TP.Normal_package; ID: GDA; INSTANCENAME: INS3009; MAKER: MAC8; PARTNAME: HK-2_M8
TP6 = TP: COMP: PRT_44; COMPONENTNAME: TP_TP.Normal_package; FUNCTION: TP_TP.Normal_package; ID: GDB; INSTANCENAME: INS3001; MAKER: MAC8; PARTNAME: HK-2_M8
TP7 = TP: COMP: PRT_44; COMPONENTNAME: TP_TP.Normal_package; FUNCTION: TP_TP.Normal_package; ID: VINAC; INSTANCENAME: INS2993; MAKER: MAC8; PARTNAME: HK-2_M8
TP8 = TP: COMP: PRT_44; COMPONENTNAME: TP_TP.Normal_package; FUNCTION: TP_TP.Normal_package; ID: VSENSE; INSTANCENAME: INS3017; MAKER: MAC8; PARTNAME: HK-2_M8
TP43 = TP: COMP: PRT_49; COMPONENTNAME: TP_TP.Normal_package; FUNCTION: TP_TP.Normal_package; ID: PN; INSTANCENAME: INS3025; MAKER: MAC8; PARTNAME: LC-22_GS
U?#5 = WAKU_DEF100: DATE: 2021-01-27; DRAWINGNUMBER: RD171-SCHEMATIC-01; FUNCTION: PFC - Controller; REVISION: 01; SAVEAREA0: 168739,-66042,466246,90057; SAVECOUNT: 5; SHEETNUMBER: 3/8; TITLE: 1.6kW 48V Output Telecomunication / Equipment Power Supply; UPDATEDATE: 2021/01/27; UPDATETIME: 15:56:17

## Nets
VCC3R3_1: R117.2 ; also on sheet 2
VCC12R0_1: R116.1 R120.1 ; also on sheet 1 5 7 8
$BN000001: R90.2 R227.1
$BN000002: R2.2 R228.1
CSA: R170.1 ; also on sheet 7
CSB: R169.1 ; also on sheet 7
GDA: IC3.14 TP5.1 ; also on sheet 7
GDB: IC3.17 TP6.1 ; also on sheet 7
PFC_OUT: R92.2 ; also on sheet 1 5 7
PFC_VIN: R95.2 ; also on sheet 7
PN: C38.1 C39.1 C40.1 C42.1 C43.1 C45.1 C47.1 C48.1 C49.1 C50.1 C66.1 C67.1 C75.1 C76.1 C77.1 D49.A IC3.16 IC11.1 R2.1 R90.1 R93.1 R96.1 R98.1 R99.1 R100.1 R101.1 R102.1 R103.1 R104.1 R174.1 R175.1 R176.1 R198.1 TP43.1 ; also on sheet 1 2 5 7 8
SIG39: R89.2 R91.1
SIG40: R91.2 R92.1
SIG43: C45.2 C46.2 IC3.11
SIG44: C46.1 R99.2
SIG45: C43.2 C44.2 IC3.12
SIG46: C44.1 R98.2
SIG47: C40.2 C41.2 IC3.3
SIG48: C41.1 R93.2
SIG49: C39.2 IC3.4 R89.1 R227.2 TP8.1
SIG50: C49.2 IC3.18
SIG51: C50.2 IC3.1 R171.1
SIG52: IC3.19 R100.2 R198.2
SIG53: IC3.7 R101.2 R176.2
SIG54: IC3.6 R102.2 R175.2
SIG55: IC3.20 R103.2 R174.2
SIG56: IC3.2 R104.2
SIG60: R94.2 R95.1
SIG61: R1.2 R94.1
SIG62: C38.2 IC3.5 R1.1 R228.2 TP7.1
SIG86: C47.2 C48.2 D49.C IC3.15 R120.2
SIG185: C67.2 IC11.3 R117.1
SIG223: C66.2 IC11.2 R130.2
SIGN256: C77.2 IC3.10 R96.2 R97.1 R177.1
SIGN260: C76.2 IC3.9 R170.2
SIGN262: C75.2 IC3.8 R169.2
VREF_PFC: C42.2 IC3.13 R97.2 R171.2 R177.2
N03591: R116.2 R130.1

Not connected (* = marked no-connect by the designer): IC11 4 5

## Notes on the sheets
sheet 6
- 1608
- 1608
- 1608
- 1608
- 1608
- 1608
- 1608
- 1608
- 1608
- 1608
- 1608
- 1608
- 1005
- 1005
- 1608
- 1608
- 1005
- 1608
- 1608
- 2102
- 1608
- 1608
- 1608
- 1608
- 1005
- 1005
- 1005
- 1608
- 1005
- 1005
- 1608
- 1005
- 1005
- 1005
- 1608
- 1608
- 1608
- 1608
- 1608
- 1608
- 1608
- 1608
- 1608
- 1608
- 1608
- 1608
- 1005
- 1005
- 3216
